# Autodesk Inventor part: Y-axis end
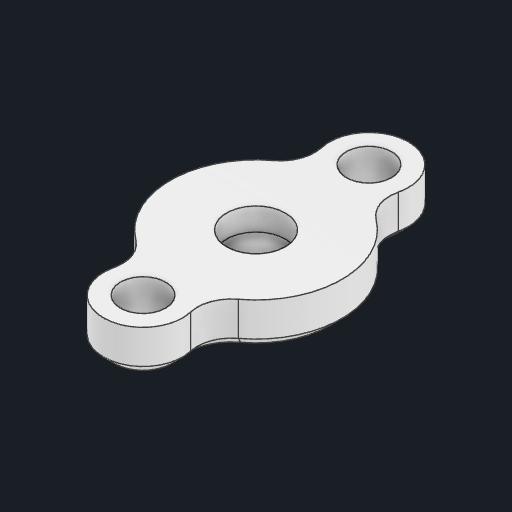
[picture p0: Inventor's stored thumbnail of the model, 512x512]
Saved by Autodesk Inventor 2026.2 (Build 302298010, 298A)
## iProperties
Created: 2026-04
Part Number: Y-axis end
Material: PBT 플라스틱
Document SubType Name: Modeling
Designer: work
Density: 1.31 g/cm^3
Appearance: 매끄러움 - 흰색
Author: work
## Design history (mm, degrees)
sketch "스케치1"
  geometry: L1 (0, 10)-(0, -10); C1 r 7.6 at (0, 0); C2 r 2 at (0, 10); C3 r 2 at (0, -10); C4 r 3.5 at (0, 10); C5 r 3.5 at (0, -10); 5 further points
  constraints: 5 centre point, 5 coincident, 2 end point, 1 midpoint, 1 vertical
  dimensions: "d0" = 20 distance of L1.start L1.end; "d1" = 4 diameter of C2; "d2" = 4 diameter of C3; "d3" = 7 diameter of C4; "d4" = 7 diameter of C5; "d5" = 15.2 diameter of C1
extrude "돌출1" new body sketch "스케치1" distance "d6" = 4; taper "d7" = 0 deg
sketch "스케치2"
  geometry: C1 r 2.6 at (0, 0); 1 further point
  constraints: 1 centre point, 1 coincident
  dimensions: "d8" = 5.2 diameter of C1
extrude "돌출2" cut sketch "스케치2" distance "d9" = 2; taper "d10" = 0 deg
fillet "모깎기1" dims "d11" = 3
chamfer "모따기1" distance "d12" = 1; stored, may be unused: second distance "d13" = 2, angle "d14" = 45 deg
node "솔리드1"
